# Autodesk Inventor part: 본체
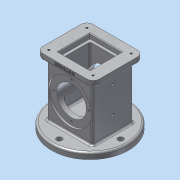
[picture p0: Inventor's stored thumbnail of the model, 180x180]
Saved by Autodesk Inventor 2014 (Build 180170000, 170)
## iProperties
Created: 2018-10
Part Number: 본체
Material: 알루미늄 6061
Document SubType Name: Modeling
Designer: 602-19
Density: 2.71 g/cm^3
Appearance: 알루미늄 - 평지
Mass: 988.22 g
Surface Area: 743.905 cm^2
Volume: 364.657 cm^3
Author: 602-19
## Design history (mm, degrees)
sketch "스케치1"
  geometry: L1 (-37, 33)-(37, 33); L2 (37, 33)-(37, -33); L3 (37, -33)-(-37, -33); L4 (-37, -33)-(-37, 33); L5 (-37, 33)-(37, -33); L6 (37, 33)-(-37, -33); 1 further point
  constraints: 12 end point, 2 midpoint, 2 parallel, 1 horizontal, 1 perpendicular
  dimensions: "d0" = 66 distance of L1.end L2.end; "d1" = 74 distance of L1.start L1.end
extrude "돌출1" new body sketch "스케치1" distance "d2" = 108; taper "d3" = 0 deg
sketch "스케치2"
  geometry: C1 r 62.5 at (0, 0); 1 further point
  constraints: 1 centre point, 1 coincident
  dimensions: "d4" = 125 diameter of C1
extrude "돌출2" join sketch "스케치2" distance "d5" = 10; taper "d6" = 0 deg
sketch "스케치3"
  geometry: L1 (-46, 41)-(46, 41); L2 (46, 41)-(46, -41); L3 (46, -41)-(-46, -41); L4 (-46, -41)-(-46, 41); L5 (-46, 41)-(46, -41); L6 (46, 41)-(-46, -41); 1 further point
  constraints: 12 end point, 2 midpoint, 2 parallel, 1 horizontal, 1 perpendicular
  dimensions: "d7" = 82 distance of L1.end L2.end; "d8" = 92 distance of L1.start L1.end
extrude "돌출3" join sketch "스케치3" distance "d9" = 10; taper "d10" = 0 deg
fillet "모깎기1" dims "d11" = 10
fillet "모깎기2" dims "d12" = 3
fillet "모깎기3" dims "d13" = 3
sketch "스케치4"
  geometry: L1 (-26, 26)-(26, 26); L2 (26, 26)-(26, -26); L3 (26, -26)-(-26, -26); L4 (-26, -26)-(-26, 26); L5 (-26, 26)-(26, -26); L6 (26, 26)-(-26, -26); 1 further point
  constraints: 12 end point, 2 midpoint, 2 parallel, 1 horizontal, 1 perpendicular
  dimensions: "d14" = 52 distance of L1.start L1.end; "d15" = 52 distance of L1.end L2.end
extrude "돌출4" cut sketch "스케치4" distance "d16" = 8; taper "d17" = 0 deg
sketch "스케치5"
  geometry: L1 (-22, 22)-(22, 22); L2 (22, 22)-(22, -22); L3 (22, -22)-(-22, -22); L4 (-22, -22)-(-22, 22); L5 (-22, 22)-(22, -22); L6 (22, 22)-(-22, -22); 1 further point
  constraints: 12 end point, 2 midpoint, 2 parallel, 1 horizontal, 1 perpendicular
  dimensions: "d18" = 44 distance of L2.end L3.end; "d19" = 44 distance of L1.end L2.end
extrude "돌출5" cut sketch "스케치5" distance "d20" = 74; taper "d21" = 0 deg
chamfer "모따기1" distance "d22" = 1; stored, may be unused: second distance "d23" = 2, angle "d24" = 45 deg
fillet "모깎기4" dims "d25" = 3
sketch "스케치6"
  geometry: L1 (34, -95)-(34, 56.625); L2 (-26.109, -41)-(126.764, -41); C1 r 35 at (34, -41)
  constraints: 4 end point, 2 point on line, 1 centre point, 1 perpendicular, 1 vertical
  dimensions: "d26" = 54 distance from line of L1.start L2; "d27" = 70 diameter of C1
extrude "돌출6" cut sketch "스케치6" distance "d28" = 3; taper "d29" = 0 deg
sketch "스케치7"
  geometry: C1 r 35 at (0, 0) reference; C2 r 24 at (0, 0); 1 further point
  constraints: 1 centre point, 1 coincident
  dimensions: "d30" = 48 diameter of C2
extrude "돌출7" cut sketch "스케치7" stored distance "d31" = 3; taper "d32" = 0 deg
sketch "스케치8"
  geometry: C1 r 35 at (34, 41); A1 r 24 centre (34, 41) between (53, 55.663) and (15, 55.663) reference; 1 further point
  constraints: 1 centre point, 1 coincident
  dimensions: "d33" = 70 diameter of C1
extrude "돌출8" cut sketch "스케치8" distance "d34" = 3; taper "d35" = 0 deg
sketch "스케치9"
  geometry: C1 r 28 at (0, 0); 1 further point
  constraints: 1 centre point, 1 coincident
  dimensions: "d36" = 56 diameter of C1
extrude "돌출9" cut sketch "스케치9" distance "d37" = 18; taper "d38" = -10 deg
sketch "스케치11" dims "d39" = 100
  geometry: L1 (0, 0)-(0, 85.068); 2 further points
  constraints: 2 end point, 1 coincident, 1 point on line, 1 vertical, 1 vertical alignment, 2 other
hole "구멍1" sketch "스케치11" at (0, 50) diameter "d40" = 9; stored, may be unused: countersink angle "d44" = 90 deg, drill point angle "d46" = 118 deg; dims "d41" = 6, "d42" = 4, "d43" = 2, "d45" = 8
hole "구멍2" diameter "d52" = 3.242; stored, may be unused: countersink angle "d56" = 90 deg, drill point angle "d58" = 118 deg; dims "d50" = 10, "d51" = 10, "d53" = 4, "d54" = 4, "d55" = 2, "d57" = 6
sketch "스케치12"
  geometry: C1 r 24 at (0, 0) reference; C2 r 35 at (0, 0) reference; 2 further points
  dimensions: "d65" = 29 distance of C1.centre point (0, 29)
hole "구멍3" sketch "스케치12" at (0, 29) diameter "d66" = 3.242; stored, may be unused: countersink angle "d70" = 90 deg, drill point angle "d72" = 118 deg; dims "d67" = 4, "d68" = 4, "d69" = 2, "d71" = 6
sketch "스케치13"
  geometry: L1 (95, 30)-(-44.757, 30); 1 further point
  constraints: 2 end point, 1 horizontal, 1 point on line
  dimensions: "d76" = 37 distance of L1.start point (58, 30)
hole "구멍4" sketch "스케치13" at (58, 30) diameter "d77" = 4.134; stored, may be unused: countersink angle "d81" = 90 deg, drill point angle "d83" = 118 deg; dims "d78" = 20, "d79" = 4, "d80" = 2, "d82" = 26
sketch "스케치14"
  geometry: L1 (36, -108)-(36, 23.076); L2 (9.831, -4)-(64.046, -4); L3 (72, 0)-(0, 0) reference; L4 (19.461, -1.519)-(52.644, -1.519); L5 (52.644, -1.519)-(52.644, -6.323); L6 (52.644, -6.323)-(19.461, -6.323); L7 (19.461, -6.323)-(19.461, -1.519)
  constraints: 4 end point, 1 perpendicular, 1 vertical, 2 other
  dimensions: "d87" = 4 distance between parallel lines of L2 L3
feature "엠보싱1" sketch "스케치14" dims "d0" = 66, "d1" = 74, "d88" = 0.5, "d89" = 0
fillet "모깎기5" dims "d90" = 3
node "솔리드1"
pattern_circular "원형 패턴1" dims angle "d48" = 360 deg
pattern_linear "직사각형 패턴1" dims "d61" = 72, "d64" = 62
pattern_circular "원형 패턴2" dims angle "d74" = 360 deg
mirror "대칭1"
pattern_linear "직사각형 패턴2" dims "d86" = 43
node "투영된 루프1"
node "투영된 루프3"
